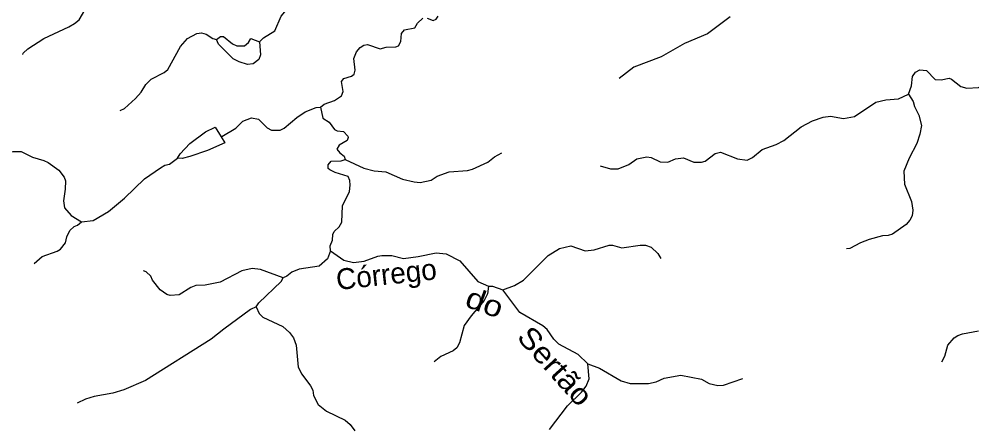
# Model space of a CAD drawing. Extents: x 577 to 602.9, y 7483.8 to 7511.6.
# Drawn here: x 589.273 to 592.922, y 7498.138 to 7499.704 of the extents above; entities that cross this region are included whole.
import ezdxf
from ezdxf.enums import TextEntityAlignment as Align

# ---------------------------------------------------------------- set-up
doc = ezdxf.new("R2010")
doc.units = 0
doc.header["$LTSCALE"] = 0.032
doc.layers.add('2', color=7, linetype='Continuous', lineweight=25)
doc.layers.add('7', color=7, linetype='Continuous', lineweight=25)
doc.layers.add('61', color=7, linetype='Continuous')

msp = doc.modelspace()

# ---------------------------------------------------------------- linework, layer by layer
at = {"layer": '2'}
for points in [[(590.0289, 7499.6255), (590.0445, 7499.6378), (590.0567, 7499.6378), (590.0902, 7499.6092), (590.1074, 7499.6018), (590.136, 7499.601), (590.1524, 7499.6141), (590.1607, 7499.6297), (590.1945, 7499.6175), (590.1981, 7499.5675), (590.1916, 7499.5495), (590.1695, 7499.5332), (590.1483, 7499.5307), (590.1164, 7499.5397), (590.0935, 7499.552), (590.0371, 7499.6075)], [(589.8805, 7499.1708), (589.89, 7499.1882), (589.9276, 7499.2275), (589.9872, 7499.2724), (590.0245, 7499.2906), (590.0472, 7499.2528), (590.0607, 7499.2303), (589.9946, 7499.2005), (589.9268, 7499.1776), (589.8981, 7499.1702)]]:
    msp.add_lwpolyline(points, close=True, dxfattribs=at)
at = {"layer": '7'}
for points in [[(589.2875, 7499.5679), (589.2884, 7499.574), (589.3063, 7499.5896), (589.3685, 7499.6296), (589.4641, 7499.6738), (589.4854, 7499.6868), (589.5033, 7499.7007), (589.5254, 7499.7383)], [(590.1945, 7499.6175), (590.2096, 7499.6321), (590.2521, 7499.659), (590.2766, 7499.7146), (590.2913, 7499.7318), (590.2995, 7499.7481)], [(590.4278, 7499.3672), (590.4417, 7499.3779), (590.481, 7499.3926), (590.5079, 7499.4097), (590.5145, 7499.4261), (590.5079, 7499.4653), (590.5169, 7499.4768), (590.5464, 7499.4849), (590.5562, 7499.4931), (590.5602, 7499.5078), (590.5553, 7499.5536), (590.5652, 7499.5781), (590.5799, 7499.5953), (590.5938, 7499.6043), (590.6077, 7499.6067), (590.6559, 7499.5896), (590.6796, 7499.5961), (590.7156, 7499.5977), (590.7262, 7499.6018), (590.7352, 7499.6182), (590.7376, 7499.6492), (590.7491, 7499.6631), (590.7891, 7499.6705), (590.7989, 7499.6885), (590.8194, 7499.7073)], [(590.8365, 7499.7073), (590.8586, 7499.6983), (590.8709, 7499.7032), (590.8782, 7499.7146)], [(591.9964, 7499.713), (591.9098, 7499.6476), (591.8215, 7499.61), (591.7324, 7499.5601), (591.627, 7499.5193), (591.5717, 7499.477)], [(589.6607, 7499.354), (589.6766, 7499.3615), (589.7191, 7499.3999), (589.7404, 7499.4244), (589.7584, 7499.4531), (589.7796, 7499.4743), (589.8295, 7499.4996), (589.8426, 7499.5111), (589.8908, 7499.5994), (589.9178, 7499.6296), (589.9537, 7499.6484), (589.9717, 7499.6509), (589.9897, 7499.6468), (590.015, 7499.6296), (590.0289, 7499.6255)], [(592.6798, 7499.4171), (592.6904, 7499.449), (592.6945, 7499.4841), (592.7059, 7499.5005), (592.7231, 7499.5095), (592.7484, 7499.507), (592.7811, 7499.4727), (592.8048, 7499.471), (592.8343, 7499.4784), (592.8441, 7499.4743), (592.8792, 7499.4457), (592.9021, 7499.4392), (592.9479, 7499.4424), (592.9847, 7499.4588)], [(591.4991, 7499.1417), (591.5379, 7499.131), (591.5673, 7499.131), (591.6082, 7499.1465), (591.6384, 7499.1694), (591.6768, 7499.1768), (591.6932, 7499.1743), (591.7283, 7499.1572), (591.7577, 7499.1563), (591.7872, 7499.1694), (591.8174, 7499.1727), (591.8575, 7499.1563), (591.8869, 7499.1563), (591.9, 7499.1604), (591.9384, 7499.1899), (591.9588, 7499.1948), (592.025, 7499.1686), (592.061, 7499.1637), (592.0814, 7499.1735), (592.119, 7499.2046), (592.173, 7499.2242), (592.2016, 7499.2389), (592.2686, 7499.2912), (592.3111, 7499.3141), (592.352, 7499.3288), (592.3806, 7499.3321), (592.4297, 7499.3239), (592.473, 7499.3313), (592.5539, 7499.386), (592.5923, 7499.395), (592.6414, 7499.3983), (592.6798, 7499.4171)], [(592.6798, 7499.4171), (592.6969, 7499.3885), (592.7027, 7499.3689), (592.719, 7499.3362), (592.7288, 7499.2969), (592.7231, 7499.2634), (592.7108, 7499.2275), (592.6814, 7499.1719), (592.661, 7499.122), (592.6643, 7499.0713), (592.6912, 7499.0051), (592.6953, 7498.9716), (592.6929, 7498.9504), (592.6847, 7498.934), (592.67, 7498.9168), (592.6177, 7498.8809), (592.6013, 7498.8752), (592.5801, 7498.8743), (592.5286, 7498.8596), (592.495, 7498.8465), (592.455, 7498.8253), (592.4423, 7498.8236)], [(590.0472, 7499.2528), (590.0492, 7499.254), (590.1033, 7499.2863), (590.1295, 7499.3133), (590.163, 7499.3255), (590.19, 7499.3206), (590.2235, 7499.2879), (590.2398, 7499.2789), (590.2725, 7499.2789), (590.2889, 7499.2863), (590.3371, 7499.3272), (590.3682, 7499.3484), (590.4115, 7499.3656), (590.4278, 7499.3672)], [(590.4278, 7499.3672), (590.436, 7499.3247), (590.4613, 7499.3092), (590.481, 7499.2806), (590.4916, 7499.2757), (590.5161, 7499.274), (590.5325, 7499.2561), (590.5341, 7499.2503), (590.53, 7499.2389), (590.4989, 7499.2209), (590.4899, 7499.2054), (590.5014, 7499.1915), (590.5186, 7499.1792), (590.5226, 7499.1661)], [(589.2096, 7499.1875), (589.2499, 7499.1964), (589.2818, 7499.1972), (589.3243, 7499.1751), (589.3685, 7499.1629), (589.3848, 7499.1547), (589.4257, 7499.1253), (589.4461, 7499.0983), (589.451, 7499.0852), (589.4502, 7499.0533), (589.4429, 7499.0084), (589.4478, 7498.9806), (589.4731, 7498.9512), (589.5123, 7498.9275)], [(590.5226, 7499.1661), (590.5929, 7499.1335), (590.633, 7499.1228), (590.678, 7499.1196), (590.7417, 7499.0909), (590.7867, 7499.0803), (590.8087, 7499.0787), (590.8512, 7499.0877), (590.8749, 7499.1024), (590.9199, 7499.1187), (590.991, 7499.1245), (591.0098, 7499.1294), (591.0679, 7499.1555), (591.094, 7499.1768), (591.1224, 7499.1923)], [(589.5123, 7498.9275), (589.5565, 7498.9332), (589.6153, 7498.9675), (589.6774, 7499.0182), (589.7535, 7499.0918), (589.8148, 7499.1343), (589.8319, 7499.1441), (589.8499, 7499.149), (589.8805, 7499.1708)], [(590.4654, 7498.8171), (590.4646, 7498.8351), (590.4736, 7498.8572), (590.4744, 7498.8792), (590.4801, 7498.8907), (590.4989, 7498.9087), (590.5088, 7498.9266), (590.5112, 7498.9888), (590.5382, 7499.0435), (590.5414, 7499.0681), (590.5398, 7499.086), (590.5341, 7499.1008), (590.4834, 7499.1163), (590.4638, 7499.1261), (590.4573, 7499.1318), (590.4564, 7499.1457), (590.4687, 7499.1596), (590.5071, 7499.1612), (590.5226, 7499.1661)], [(589.331, 7498.7679), (589.3619, 7498.7942), (589.4191, 7498.8147), (589.4322, 7498.8228), (589.451, 7498.8465), (589.4559, 7498.8702), (589.4682, 7498.894), (589.4845, 7498.9103), (589.4968, 7498.9144), (589.5123, 7498.9275)], [(590.4654, 7498.8171), (590.454, 7498.7861), (590.4229, 7498.7583), (590.3461, 7498.7468), (590.3183, 7498.7346), (590.2987, 7498.719), (590.284, 7498.7125)], [(590.4654, 7498.8171), (590.5169, 7498.7811), (590.5537, 7498.7713), (590.5946, 7498.7771), (590.6469, 7498.7967), (590.6624, 7498.7991), (590.7008, 7498.7983), (590.745, 7498.7877), (590.8014, 7498.795), (590.87, 7498.8089), (590.9085, 7498.8049), (590.9616, 7498.7787), (591.0294, 7498.6994), (591.0703, 7498.6814)], [(591.1259, 7498.6675), (591.1708, 7498.6839), (591.2044, 7498.7043), (591.2992, 7498.7991), (591.3433, 7498.8253), (591.3866, 7498.8351), (591.4406, 7498.8171), (591.4757, 7498.8204), (591.533, 7498.8384), (591.546, 7498.8384), (591.5812, 7498.8277), (591.6515, 7498.8384), (591.6719, 7498.8376), (591.6932, 7498.8302), (591.7193, 7498.8057), (591.7302, 7498.787)], [(590.284, 7498.7125), (590.1973, 7498.7444), (590.1654, 7498.7485), (590.1262, 7498.7403), (590.0436, 7498.697), (589.9864, 7498.6855), (589.9505, 7498.6839), (589.9308, 7498.6765), (589.8867, 7498.6479), (589.8516, 7498.6455), (589.8385, 7498.6495), (589.8131, 7498.6675), (589.7845, 7498.7043), (589.7772, 7498.7198), (589.76, 7498.7362), (589.7494, 7498.7397)], [(590.1818, 7498.6021), (590.1916, 7498.6169), (590.2766, 7498.6986), (590.284, 7498.7125)], [(591.0703, 7498.6814), (591.067, 7498.6512), (591.054, 7498.6258), (591.0049, 7498.5678), (590.9779, 7498.5302), (590.96, 7498.464), (590.9501, 7498.4452), (590.9354, 7498.4329), (590.888, 7498.4117), (590.8631, 7498.3913)], [(591.0703, 7498.6814), (591.0858, 7498.6806), (591.1259, 7498.6675)], [(591.4512, 7498.3839), (591.4136, 7498.419), (591.3401, 7498.4591), (591.3213, 7498.4779), (591.2951, 7498.5155), (591.2787, 7498.5294), (591.1913, 7498.5809), (591.1259, 7498.6675)], [(590.1818, 7498.6021), (590.1589, 7498.5915), (590.0575, 7498.5163), (590.0085, 7498.4787), (589.7576, 7498.3201), (589.6742, 7498.2842), (589.6317, 7498.2719), (589.5606, 7498.2588), (589.5279, 7498.249), (589.4963, 7498.2337)], [(590.1818, 7498.6021), (590.1924, 7498.5768), (590.2071, 7498.5629), (590.2831, 7498.5261), (590.3093, 7498.504), (590.324, 7498.4836), (590.3338, 7498.4558), (590.342, 7498.3708), (590.3559, 7498.3438), (590.3894, 7498.2997), (590.3976, 7498.2833), (590.4009, 7498.2621), (590.4188, 7498.2278), (590.4507, 7498.2024), (590.5226, 7498.1681), (590.5414, 7498.1509), (590.5594, 7498.1272)], [(592.807, 7498.3917), (592.8179, 7498.4125), (592.8302, 7498.4558), (592.8539, 7498.4828), (592.8686, 7498.4926), (592.8866, 7498.4983), (592.9471, 7498.5098)], [(591.3041, 7498.1321), (591.3736, 7498.2229), (591.4275, 7498.2752), (591.4447, 7498.2981), (591.4561, 7498.3267), (591.4512, 7498.3839)], [(591.4512, 7498.3839), (591.4954, 7498.3675), (591.5787, 7498.3185), (591.6139, 7498.3087), (591.6842, 7498.3087), (591.7128, 7498.3144), (591.7439, 7498.3283), (591.8068, 7498.3397), (591.8861, 7498.325), (591.9163, 7498.3087), (591.949, 7498.3013), (591.9703, 7498.3021), (592.0444, 7498.3272)]]:
    msp.add_lwpolyline(points, dxfattribs=at)

# ---------------------------------------------------------------- texts
at = {"layer": '61'}
msp.add_text('Córrego', height=0.08, rotation=6.208, dxfattribs=at).set_placement((590.6838, 7498.687), align=Align.CENTER)
for s, rotation, width, p in [('do', 339.813, 1.2, (591.0426, 7498.5809)), ('Sertão', 311.976, 1.15, (591.2966, 7498.3485))]:
    msp.add_text(s, height=0.08, rotation=rotation, dxfattribs=dict(at, width=width)).set_placement(p, align=Align.CENTER)

doc.saveas('drawing.dxf')
